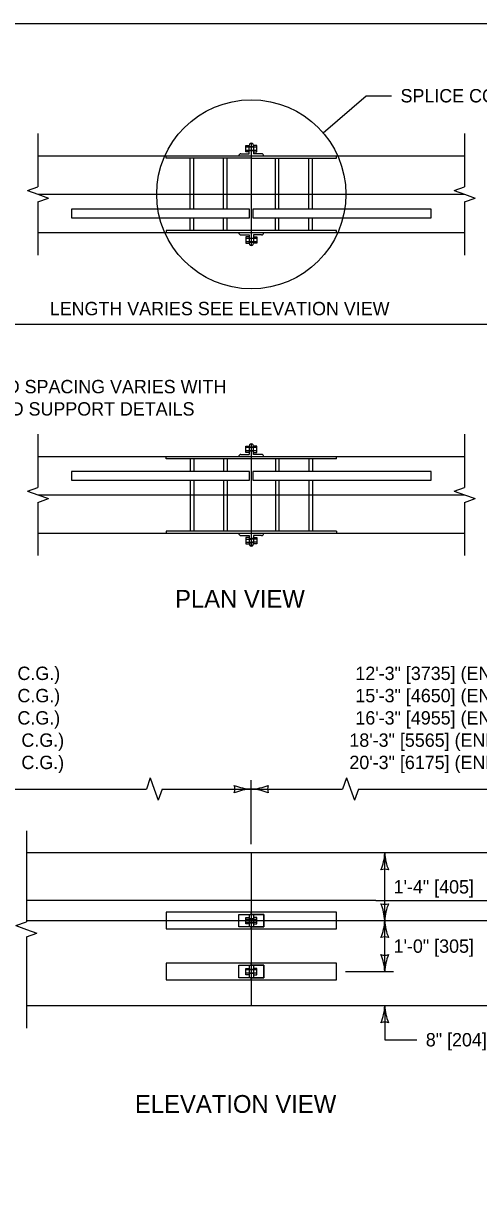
# Model space of a CAD drawing. Extents: x 49991.4 to 50021, y 49987.6 to 50011.4.
# Drawn here: x 50003.67 to 50005.71, y 49993.74 to 49999 of the extents above; entities that cross this region are included whole.
import ezdxf

# ---------------------------------------------------------------- set-up
doc = ezdxf.new("R2010")
doc.units = 0
for name, color, linetype in [('Level 1', 7, 'Continuous'), ('Level 2', 7, 'Continuous'), ('Level 3', 7, 'Continuous'), ('Level 4', 7, 'Continuous'), ('Level 5', 7, 'Continuous'), ('Level 6', 7, 'Continuous')]:
    doc.layers.add(name, color=color, linetype=linetype)

msp = doc.modelspace()

# ---------------------------------------------------------------- linework, layer by layer
at = {"layer": 'Level 1'}
for p, q in [((50004.6937, 49998.4616), (50004.6937, 49998.4043)), ((50004.6472, 49998.414), (50004.684, 49998.414)), ((50004.669, 49998.423), (50004.669, 49998.4515)), ((50004.669, 49998.4515), (50004.684, 49998.4515)), ((50004.669, 49998.4444), (50004.7185, 49998.4444)), ((50004.669, 49998.4301), (50004.7185, 49998.4301)), ((50004.684, 49998.423), (50004.669, 49998.423)), ((50004.684, 49998.414), (50004.684, 49998.4515)), ((50004.7185, 49998.4515), (50004.7035, 49998.4515)), ((50004.7035, 49998.4515), (50004.7035, 49998.414)), ((50004.7035, 49998.423), (50004.7185, 49998.423)), ((50004.7402, 49998.414), (50004.7035, 49998.414)), ((50004.7185, 49998.423), (50004.7185, 49998.4515)), ((50003.7363, 49998.4043), (50005.6511, 49998.4043)), ((50004.3112, 49998.3945), (50004.3112, 49998.4043)), ((50004.6937, 49998.3945), (50004.3112, 49998.3945)), ((50004.4195, 49998.1646), (50004.4195, 49998.3945)), ((50004.4355, 49998.1646), (50004.4355, 49998.3945)), ((50004.5695, 49998.1646), (50004.5695, 49998.3945)), ((50004.5855, 49998.1646), (50004.5855, 49998.3945)), ((50004.6937, 49998.4043), (50004.6937, 49998.0593)), ((50004.6937, 49998.3945), (50005.0762, 49998.3945)), ((50004.802, 49998.1646), (50004.802, 49998.3945)), ((50004.818, 49998.1646), (50004.818, 49998.3945)), ((50004.952, 49998.1646), (50004.952, 49998.3945)), ((50004.968, 49998.1646), (50004.968, 49998.3945)), ((50005.0762, 49998.3945), (50005.0762, 49998.4043)), ((50003.7363, 49998.2318), (50005.6511, 49998.2318)), ((50004.6864, 49998.1646), (50003.8863, 49998.1646)), ((50003.8863, 49998.1646), (50003.8863, 49998.1264)), ((50004.6864, 49998.1264), (50004.6864, 49998.1646)), ((50005.5011, 49998.1646), (50004.701, 49998.1646)), ((50004.701, 49998.1646), (50004.701, 49998.1264)), ((50005.5011, 49998.1264), (50005.5011, 49998.1646)), ((50003.8863, 49998.1264), (50004.6864, 49998.1264)), ((50004.4195, 49998.069), (50004.4195, 49998.1264)), ((50004.4355, 49998.069), (50004.4355, 49998.1264)), ((50004.5695, 49998.069), (50004.5695, 49998.1264)), ((50004.5855, 49998.069), (50004.5855, 49998.1264)), ((50004.701, 49998.1264), (50005.5011, 49998.1264)), ((50004.802, 49998.069), (50004.802, 49998.1264)), ((50004.818, 49998.069), (50004.818, 49998.1264)), ((50004.952, 49998.069), (50004.952, 49998.1264)), ((50004.968, 49998.069), (50004.968, 49998.1264)), ((50005.6511, 49998.0593), (50003.7363, 49998.0593)), ((50004.6937, 49998.069), (50004.3112, 49998.069)), ((50004.3112, 49998.069), (50004.3112, 49998.0593)), ((50004.6472, 49998.0495), (50004.684, 49998.0495)), ((50004.684, 49998.0405), (50004.669, 49998.0405)), ((50004.669, 49998.0405), (50004.669, 49998.012)), ((50004.684, 49998.0495), (50004.684, 49998.012)), ((50005.0762, 49998.069), (50004.6937, 49998.069)), ((50004.6937, 49998.0593), (50004.6937, 49998.0022)), ((50004.7402, 49998.0495), (50004.7035, 49998.0495)), ((50004.7035, 49998.0495), (50004.7035, 49998.012)), ((50004.7035, 49998.0405), (50004.7185, 49998.0405)), ((50004.7185, 49998.0405), (50004.7185, 49998.012)), ((50005.0762, 49998.0593), (50005.0762, 49998.069)), ((50004.7185, 49998.0334), (50004.669, 49998.0334)), ((50004.7185, 49998.0191), (50004.669, 49998.0191)), ((50004.669, 49998.012), (50004.684, 49998.012)), ((50004.7185, 49998.012), (50004.7035, 49998.012)), ((50004.669, 49997.073), (50004.669, 49997.1015)), ((50004.669, 49997.1015), (50004.684, 49997.1015)), ((50004.7185, 49997.0943), (50004.669, 49997.0943)), ((50004.684, 49997.1015), (50004.684, 49997.064)), ((50004.6937, 49997.1113), (50004.6937, 49997.0542)), ((50004.7185, 49997.1015), (50004.7035, 49997.1015)), ((50004.7035, 49997.064), (50004.7035, 49997.1015)), ((50004.7185, 49997.073), (50004.7185, 49997.1015)), ((50003.7363, 49997.0542), (50005.6511, 49997.0542)), ((50004.3112, 49997.0445), (50004.3112, 49997.0542)), ((50005.0762, 49997.0445), (50004.3112, 49997.0445)), ((50004.4195, 49997.0445), (50004.4195, 49996.9871)), ((50004.4355, 49997.0445), (50004.4355, 49996.9871)), ((50004.5695, 49997.0445), (50004.5695, 49996.9871)), ((50004.5855, 49997.0445), (50004.5855, 49996.9871)), ((50004.6472, 49997.064), (50004.684, 49997.064)), ((50004.7185, 49997.0801), (50004.669, 49997.0801)), ((50004.684, 49997.073), (50004.669, 49997.073)), ((50004.6937, 49997.0542), (50004.6937, 49996.7092)), ((50004.7035, 49997.073), (50004.7185, 49997.073)), ((50004.7402, 49997.064), (50004.7035, 49997.064)), ((50004.802, 49997.0445), (50004.802, 49996.9871)), ((50004.818, 49997.0445), (50004.818, 49996.9871)), ((50004.952, 49997.0445), (50004.952, 49996.9871)), ((50004.968, 49997.0445), (50004.968, 49996.9871)), ((50005.0762, 49997.0445), (50005.0762, 49997.0542)), ((50004.6864, 49996.9871), (50003.8863, 49996.9871)), ((50003.8863, 49996.9871), (50003.8863, 49996.9488)), ((50004.6864, 49996.9488), (50004.6864, 49996.9871)), ((50005.5011, 49996.9871), (50004.701, 49996.9871)), ((50004.701, 49996.9871), (50004.701, 49996.9488)), ((50005.5011, 49996.9488), (50005.5011, 49996.9871)), ((50003.8863, 49996.9488), (50004.6864, 49996.9488)), ((50004.4195, 49996.9488), (50004.4195, 49996.719)), ((50004.4355, 49996.9488), (50004.4355, 49996.719)), ((50004.5695, 49996.9488), (50004.5695, 49996.719)), ((50004.5855, 49996.9488), (50004.5855, 49996.719)), ((50004.701, 49996.9488), (50005.5011, 49996.9488)), ((50004.802, 49996.9488), (50004.802, 49996.719)), ((50004.818, 49996.9488), (50004.818, 49996.719)), ((50004.952, 49996.9488), (50004.952, 49996.719)), ((50004.968, 49996.9488), (50004.968, 49996.719)), ((50003.7367, 49996.8817), (50005.6515, 49996.8817)), ((50005.6511, 49996.7092), (50003.7363, 49996.7092)), ((50005.0762, 49996.719), (50004.3112, 49996.719)), ((50004.3112, 49996.719), (50004.3112, 49996.7092)), ((50004.6472, 49996.6995), (50004.684, 49996.6995)), ((50004.684, 49996.6905), (50004.669, 49996.6905)), ((50004.669, 49996.6905), (50004.669, 49996.662)), ((50004.669, 49996.6833), (50004.6937, 49996.6833)), ((50004.684, 49996.6995), (50004.684, 49996.662)), ((50004.6937, 49996.7092), (50004.6937, 49996.6522)), ((50004.7185, 49996.6833), (50004.6937, 49996.6833)), ((50004.7402, 49996.6995), (50004.7035, 49996.6995)), ((50004.7035, 49996.6995), (50004.7035, 49996.662)), ((50004.7035, 49996.6905), (50004.7185, 49996.6905)), ((50004.7185, 49996.6905), (50004.7185, 49996.662)), ((50005.0762, 49996.719), (50005.0762, 49996.7092)), ((50004.669, 49996.6691), (50004.6937, 49996.6691)), ((50004.669, 49996.662), (50004.684, 49996.662)), ((50004.7185, 49996.6691), (50004.6937, 49996.6691)), ((50004.7185, 49996.662), (50004.7035, 49996.662)), ((50006.0262, 49995.2739), (50003.6843, 49995.2739)), ((50004.6937, 49995.2739), (50004.6937, 49994.5876)), ((50004.6937, 49995.0076), (50004.3112, 49995.0076)), ((50004.3112, 49995.0076), (50004.3112, 49994.9326)), ((50004.6375, 49994.942), (50004.6375, 49994.9982)), ((50004.6375, 49994.9982), (50004.6937, 49994.9982)), ((50004.6375, 49994.942), (50004.6375, 49994.9982)), ((50004.6375, 49994.9982), (50004.6937, 49994.9982)), ((50004.684, 49994.9982), (50004.684, 49994.942)), ((50004.6937, 49995.0076), (50004.6937, 49994.9326)), ((50004.6937, 49995.0076), (50004.6937, 49994.9326)), ((50004.6937, 49994.9982), (50004.6937, 49995.0076)), ((50005.0762, 49995.0076), (50004.6937, 49995.0076)), ((50004.6937, 49995.0076), (50004.6937, 49994.9982)), ((50004.75, 49994.9982), (50004.6937, 49994.9982)), ((50004.6937, 49994.9982), (50004.6937, 49994.942)), ((50004.6937, 49994.9982), (50004.6937, 49994.942)), ((50004.6937, 49994.9982), (50004.75, 49994.9982)), ((50004.7035, 49994.9982), (50004.7035, 49994.942)), ((50004.75, 49994.942), (50004.75, 49994.9982)), ((50004.75, 49994.9982), (50004.75, 49994.942)), ((50005.0762, 49994.9326), (50005.0762, 49995.0076)), ((50004.6937, 49994.942), (50004.6375, 49994.942)), ((50004.6937, 49994.942), (50004.6375, 49994.942)), ((50004.669, 49994.9772), (50004.7185, 49994.9772)), ((50004.669, 49994.963), (50004.7185, 49994.963)), ((50004.6937, 49994.942), (50004.75, 49994.942)), ((50004.6937, 49994.9326), (50004.6937, 49994.942)), ((50004.75, 49994.942), (50004.6937, 49994.942)), ((50004.6937, 49994.942), (50004.6937, 49994.9326)), ((50004.3112, 49994.9326), (50004.6937, 49994.9326)), ((50004.6937, 49994.9326), (50005.0762, 49994.9326)), ((50004.6937, 49994.7789), (50004.3112, 49994.7789)), ((50004.3112, 49994.7789), (50004.3112, 49994.7039)), ((50004.6937, 49994.7789), (50004.6937, 49994.7039)), ((50004.6937, 49994.7789), (50004.6937, 49994.7039)), ((50004.6937, 49994.7695), (50004.6937, 49994.7789)), ((50005.0762, 49994.7789), (50004.6937, 49994.7789)), ((50004.6937, 49994.7789), (50004.6937, 49994.7695)), ((50005.0762, 49994.7039), (50005.0762, 49994.7789)), ((50004.6375, 49994.7132), (50004.6375, 49994.7695)), ((50004.6375, 49994.7695), (50004.6937, 49994.7695)), ((50004.6375, 49994.7132), (50004.6375, 49994.7695)), ((50004.6375, 49994.7695), (50004.6937, 49994.7695)), ((50004.7185, 49994.7485), (50004.669, 49994.7485)), ((50004.7185, 49994.7342), (50004.669, 49994.7342)), ((50004.684, 49994.7695), (50004.684, 49994.7132)), ((50004.75, 49994.7695), (50004.6937, 49994.7695)), ((50004.6937, 49994.7695), (50004.6937, 49994.7132)), ((50004.6937, 49994.7695), (50004.6937, 49994.7132)), ((50004.6937, 49994.7695), (50004.75, 49994.7695)), ((50004.7035, 49994.7695), (50004.7035, 49994.7132)), ((50004.75, 49994.7132), (50004.75, 49994.7695)), ((50004.75, 49994.7695), (50004.75, 49994.7132)), ((50004.3112, 49994.7039), (50004.6937, 49994.7039)), ((50004.6937, 49994.7132), (50004.6375, 49994.7132)), ((50004.6937, 49994.7132), (50004.6375, 49994.7132)), ((50004.6937, 49994.7132), (50004.75, 49994.7132)), ((50004.6937, 49994.7039), (50004.6937, 49994.7132)), ((50004.75, 49994.7132), (50004.6937, 49994.7132)), ((50004.6937, 49994.7132), (50004.6937, 49994.7039)), ((50004.6937, 49994.7039), (50005.0762, 49994.7039)), ((50006.0262, 49994.5876), (50003.6843, 49994.5876))]:
    msp.add_line(p, q, dxfattribs=at)
for points in [[(49999.3835, 49998.9992), (50016.7501, 49998.9992), (50016.7501, 49987.7988), (49999.3835, 49987.7988)], [(50004.684, 49994.9559), (50004.669, 49994.9559), (50004.669, 49994.9844), (50004.684, 49994.9844)], [(50004.7035, 49994.9559), (50004.7185, 49994.9559), (50004.7185, 49994.9844), (50004.7035, 49994.9844)], [(50004.684, 49994.7271), (50004.669, 49994.7271), (50004.669, 49994.7556), (50004.684, 49994.7556)], [(50004.7035, 49994.7271), (50004.7185, 49994.7271), (50004.7185, 49994.7556), (50004.7035, 49994.7556)]]:
    msp.add_lwpolyline(points, close=True, dxfattribs=at)
for centre, radius, start, end in [((50004.6937, 49998.4518), 0.00976, 358.2093, 181.7907), ((50004.6472, 49998.4043), 0.00975, 90, 180), ((50004.7402, 49998.4043), 0.00975, 0, 90), ((50004.6472, 49998.0593), 0.00975, 180, 270), ((50004.7402, 49998.0593), 0.00975, 270, 0), ((50004.6937, 49998.0119), 0.00975, 179.6701, 0.3299), ((50004.6937, 49997.1015), 0.00975, 359.6718, 180.3282), ((50004.6472, 49997.0542), 0.00975, 90, 180), ((50004.7402, 49997.0542), 0.00975, 0, 90), ((50004.6472, 49996.7092), 0.00975, 180, 270), ((50004.7402, 49996.7092), 0.00975, 270, 0), ((50004.6937, 49996.6619), 0.00975, 179.692, 0.308)]:
    msp.add_arc(centre, radius, start, end, dxfattribs=at)
at = {"layer": 'Level 3'}
for p, q in [((50005.0159, 49998.5082), (50005.2097, 49998.6745)), ((50005.2097, 49998.6745), (50005.3235, 49998.6745)), ((50003.5709, 49997.6488), (50005.8224, 49997.6488)), ((50004.2405, 49995.6107), (50004.2228, 49995.5607)), ((50004.2405, 49995.6107), (50004.2582, 49995.5607)), ((50004.6937, 49995.3139), (50004.6937, 49995.6008)), ((50005.1213, 49995.6107), (50005.1036, 49995.5607)), ((50005.1213, 49995.6107), (50005.139, 49995.5607)), ((50001.9713, 49995.5607), (50004.2228, 49995.5607)), ((50004.2582, 49995.5607), (50004.276, 49995.5107)), ((50004.2937, 49995.5607), (50004.276, 49995.5107)), ((50004.2937, 49995.5607), (50004.6937, 49995.5608)), ((50004.6937, 49995.5608), (50005.1036, 49995.5607)), ((50005.139, 49995.5607), (50005.1568, 49995.5107)), ((50005.1745, 49995.5607), (50005.1568, 49995.5107)), ((50005.1745, 49995.5607), (50007.426, 49995.5607)), ((50005.2925, 49994.9701), (50005.2925, 49995.2739)), ((50005.2925, 49994.7414), (50005.2925, 49994.9701)), ((50005.2925, 49994.5876), (50005.2925, 49994.4353)), ((50005.2925, 49994.4353), (50005.4369, 49994.4353))]:
    msp.add_line(p, q, dxfattribs=at)
msp.add_circle((50004.6937, 49998.2318), 0.4245, dxfattribs=at)
for centre, radius, start, end in [((50004.7029, 49995.7829), 0.2223, 247.456, 267.6395), ((50004.5655, 49995.5608), 0.0548, 342.1388, 17.8612), ((50004.6846, 49995.7829), 0.2223, 272.3605, 292.544), ((50004.8219, 49995.5608), 0.0548, 162.1388, 197.8612), ((50004.7052, 49995.3281), 0.233, 92.8273, 112.0772), ((50004.6822, 49995.3281), 0.233, 67.9228, 87.1727), ((50005.0704, 49995.283), 0.2223, 337.456, 357.6395), ((50005.5252, 49995.2854), 0.233, 182.8273, 202.0772), ((50005.2925, 49995.1457), 0.0548, 72.1388, 107.8612), ((50005.2925, 49995.0983), 0.0548, 252.1388, 287.8612), ((50005.0598, 49994.9586), 0.233, 2.8273, 22.0772), ((50005.5147, 49994.961), 0.2223, 157.456, 177.6395), ((50005.0704, 49994.9793), 0.2223, 337.456, 357.6395), ((50005.5252, 49994.9816), 0.233, 182.8273, 202.0772), ((50005.2925, 49994.8419), 0.0548, 72.1388, 107.8612), ((50005.0704, 49994.7322), 0.2223, 2.3605, 22.544), ((50005.2925, 49994.8696), 0.0548, 252.1388, 287.8612), ((50005.5252, 49994.7299), 0.233, 157.9228, 177.1727), ((50005.0704, 49994.5968), 0.2223, 337.456, 357.6395), ((50005.5252, 49994.5991), 0.233, 182.8273, 202.0772), ((50005.2925, 49994.4594), 0.0548, 72.1388, 107.8612)]:
    msp.add_arc(centre, radius, start, end, dxfattribs=at)
at = {"layer": 'Level 4'}
for p, q in [((50004.684, 49998.4466), (50004.7035, 49998.4466)), ((50004.684, 49998.4279), (50004.7035, 49998.4279)), ((50004.684, 49998.0356), (50004.7035, 49998.0356)), ((50004.684, 49998.0169), (50004.7035, 49998.0169)), ((50004.7035, 49997.0966), (50004.684, 49997.0966)), ((50004.7035, 49997.0778), (50004.684, 49997.0778)), ((50004.684, 49996.6856), (50004.6937, 49996.6856)), ((50004.7035, 49996.6856), (50004.6937, 49996.6856)), ((50004.684, 49996.6668), (50004.6937, 49996.6668)), ((50004.7035, 49996.6668), (50004.6937, 49996.6668)), ((50005.2526, 49995.0601), (50003.6843, 49995.0601)), ((50005.2526, 49995.0601), (50006.0262, 49995.0601)), ((50003.6843, 49994.9701), (50006.0262, 49994.9701)), ((50004.684, 49994.9795), (50004.7035, 49994.9795)), ((50004.684, 49994.9607), (50004.7035, 49994.9607)), ((50004.7035, 49994.7507), (50004.684, 49994.7507)), ((50004.7035, 49994.732), (50004.684, 49994.732))]:
    msp.add_line(p, q, dxfattribs=at)
at = {"layer": 'Level 5'}
msp.add_line((50005.1162, 49994.7414), (50005.3325, 49994.7414), dxfattribs=at)
at = {"layer": 'Level 6'}
for p, q in [((50003.7363, 49998.5043), (50003.7363, 49998.2652)), ((50005.6511, 49998.5043), (50005.6511, 49998.2652)), ((50003.6892, 49998.2485), (50003.7363, 49998.2652)), ((50005.604, 49998.2485), (50005.6511, 49998.2652)), ((50003.6892, 49998.2485), (50003.7363, 49998.2318)), ((50003.7363, 49998.2318), (50003.7834, 49998.2151)), ((50003.7363, 49998.1984), (50003.7834, 49998.2151)), ((50003.7363, 49998.1984), (50003.7363, 49997.9593)), ((50005.604, 49998.2485), (50005.6511, 49998.2318)), ((50005.6511, 49998.2318), (50005.6982, 49998.2151)), ((50005.6511, 49998.1984), (50005.6982, 49998.2151)), ((50005.6511, 49998.1984), (50005.6511, 49997.9593)), ((50003.7363, 49997.1542), (50003.7363, 49996.9152)), ((50005.6511, 49997.1542), (50005.6511, 49996.9152)), ((50003.6892, 49996.8985), (50003.7363, 49996.9152)), ((50003.6892, 49996.8985), (50003.7363, 49996.8818)), ((50003.7363, 49996.8818), (50003.7834, 49996.8651)), ((50005.604, 49996.8985), (50005.6511, 49996.9152)), ((50005.604, 49996.8985), (50005.6511, 49996.8818)), ((50005.6511, 49996.8818), (50005.6982, 49996.8651)), ((50003.7363, 49996.8484), (50003.7834, 49996.8651)), ((50003.7363, 49996.8484), (50003.7363, 49996.6092)), ((50005.6511, 49996.8484), (50005.6982, 49996.8651)), ((50005.6511, 49996.8484), (50005.6511, 49996.6092)), ((50003.6843, 49995.3739), (50003.6843, 49994.9644)), ((50003.6372, 49994.9477), (50003.6843, 49994.9644)), ((50003.6372, 49994.9477), (50003.6843, 49994.931)), ((50003.6843, 49994.931), (50003.7314, 49994.9143)), ((50003.6843, 49994.8976), (50003.7314, 49994.9143)), ((50003.6843, 49994.8976), (50003.6843, 49994.4876))]:
    msp.add_line(p, q, dxfattribs=at)

# ---------------------------------------------------------------- texts
at = {"layer": 'Level 2'}
for s, height, p in [('SPLICE CONNECTION', 0.06, (50005.3635, 49998.6445)), ('LENGTH VARIES SEE ELEVATION VIEW', 0.06, (50003.7894, 49997.6888)), ('LAG PLATE SIZE AND SPACING VARIES WITH', 0.06, (50002.825, 49997.3383)), ('C.G. WIDTH, SEE END SUPPORT DETAILS', 0.06, (50002.825, 49997.2383)), ('PLAN VIEW', 0.08, (50004.3515, 49996.3755)), ('12\'-3" [3735] (END SUPPORT FOR 24\' [7.2 m] C.G.)', 0.06, (50001.9578, 49996.0507)), ('12\'-3" [3735] (END SUPPORT FOR 24\' [7.2 m] C.G.)', 0.06, (50005.1609, 49996.0507)), ('15\'-3" [4650] (END SUPPORT FOR 30\' [9.0 m] C.G.)', 0.06, (50001.9578, 49995.9507)), ('15\'-3" [4650] (END SUPPORT FOR 30\' [9.0 m] C.G.)', 0.06, (50005.1609, 49995.9507)), ('16\'-3" [4955] (END SUPPORT FOR 32\' [9.6 m] C.G.)', 0.06, (50001.9578, 49995.8507)), ('16\'-3" [4955] (END SUPPORT FOR 32\' [9.6 m] C.G.)', 0.06, (50005.1609, 49995.8507)), ('18\'-3" [5565] (END SUPPORT FOR 36\' [10.8 m] C.G.)', 0.06, (50001.9309, 49995.7507)), ('18\'-3" [5565] (END SUPPORT FOR 36\' [10.8 m] C.G.)', 0.06, (50005.134, 49995.7507)), ('20\'-3" [6175] (END SUPPORT FOR 40\' [12.0 m] C.G.)', 0.06, (50001.9309, 49995.6507)), ('20\'-3" [6175] (END SUPPORT FOR 40\' [12.0 m] C.G.)', 0.06, (50005.134, 49995.6507)), ('1\'-4" [405]', 0.06, (50005.3325, 49995.092)), ('1\'-0" [305]', 0.06, (50005.3325, 49994.8257)), ('8" [204]', 0.06, (50005.4769, 49994.4053)), ('ELEVATION VIEW', 0.08, (50004.1716, 49994.1069))]:
    msp.add_text(s, height=height, dxfattribs=at).set_placement(p)

doc.saveas('drawing.dxf')
